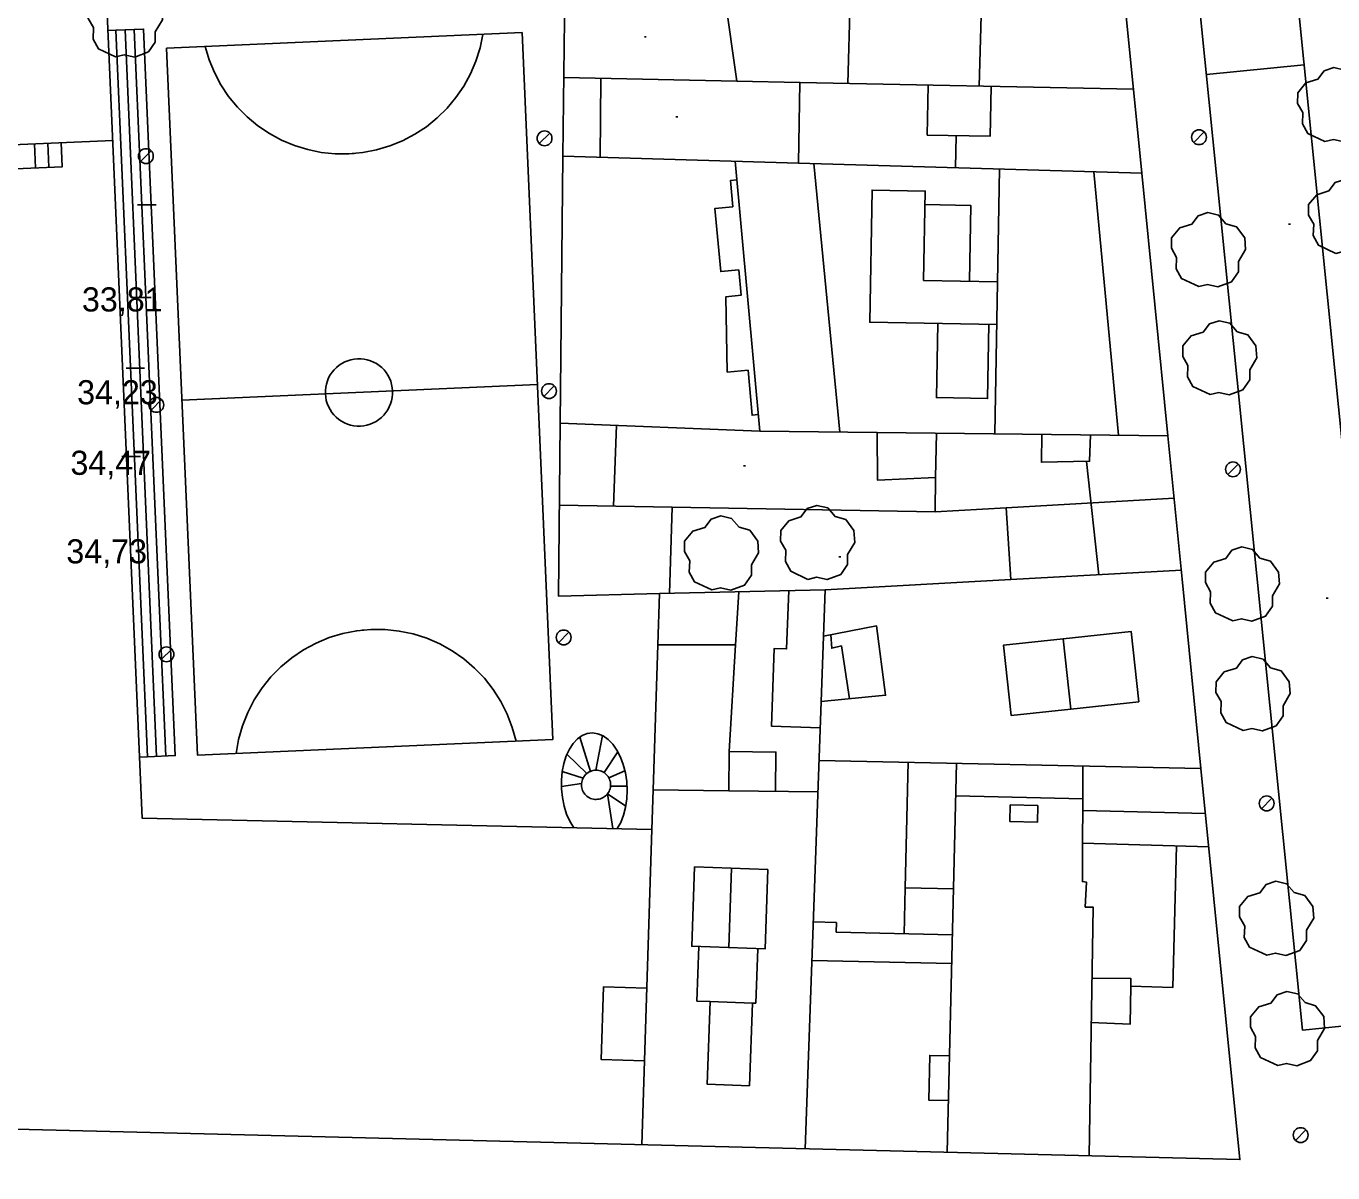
# Model space of a CAD drawing. Extents: x 431390 to 432653, y 4586754 to 4589600.
# Drawn here: x 431799.8 to 431870.2, y 4586845.3 to 4586907.1 of the extents above; entities that cross this region are included whole.
import ezdxf

# ---------------------------------------------------------------- set-up
doc = ezdxf.new("R2010")
doc.units = 0
for name, color, linetype in [('COM_17LS_LN', 7, 'Continuous'), ('COM_51_LN', 7, 'Continuous'), ('CON_01_LN', 7, 'Continuous'), ('CON_01FI_LN', 7, 'Continuous'), ('CON_03_LN', 7, 'Continuous'), ('CON_04_LN', 7, 'Continuous'), ('CON_07_LN', 7, 'Continuous'), ('CON_16_LN', 7, 'Continuous'), ('CON_18LS_LN', 7, 'Continuous'), ('CON_23_LN', 7, 'Continuous'), ('CON_24LS_LN', 7, 'Continuous'), ('CON_29_LN', 7, 'Continuous'), ('ENE_06_PT', 7, 'Continuous'), ('ORO_03_PT', 7, 'Continuous'), ('ORO_04_PT', 7, 'Continuous'), ('ORO_04_TX', 7, 'Continuous'), ('VEG_03_PT', 7, 'Continuous')]:
    doc.layers.add(name, color=color, linetype=linetype)

msp = doc.modelspace()

# ---------------------------------------------------------------- linework, layer by layer
at = {"layer": 'COM_17LS_LN'}
for points in [[(431853.209, 4587026.07), (431851.172, 4587025.865), (431854.479, 4586993.032), (431857.953, 4586958.536), (431861.124, 4586927.05), (431865.053, 4586888.028), (431868.58, 4586853.01), (431870.706, 4586853.224), (431871.5, 4586845.327)], [(431874.91, 4586845.69), (431873.853, 4586853.541), (431873.729, 4586854.767), (431875.087, 4586854.904), (431874.927, 4586856.495), (431873.569, 4586856.358), (431870.326, 4586888.559), (431867.823, 4586913.416), (431874.552, 4586914.603), (431895.864, 4586918.311), (431912.821, 4586921.261), (431929.172, 4586924.106), (431935.982, 4586925.291)]]:
    msp.add_lwpolyline(points, dxfattribs=at)
at = {"layer": 'COM_51_LN'}
msp.add_lwpolyline([(431863.395, 4586904.496), (431868.668, 4586905.027)], dxfattribs=at)
at = {"layer": 'CON_01_LN'}
for points in [[(431859.921, 4586899.186), (431858.937, 4586909.088)], [(431859.921, 4586899.186), (431861.326, 4586885.04)], [(431862.094, 4586877.312), (431861.326, 4586885.04)], [(431862.094, 4586877.312), (431863.106, 4586867.117)], [(431797.74, 4586847.72), (431865.2, 4586846.04), (431863.106, 4586867.117)]]:
    msp.add_lwpolyline(points, dxfattribs=at)
at = {"layer": 'CON_01FI_LN'}
for points in [[(431801.98, 4586957.34), (431806.03, 4586864.43), (431833.508, 4586863.83), (431833.576, 4586865.966), (431837.653, 4586865.916), (431837.679, 4586868.022), (431838.021, 4586873.777), (431833.823, 4586873.778), (431833.91, 4586876.529), (431842.85, 4586876.74), (431852.851, 4586877.287), (431852.6, 4586881.16), (431848.78, 4586880.94), (431848.8, 4586882.78), (431845.66, 4586882.65), (431845.641, 4586885.215), (431839.319, 4586885.285), (431828.566, 4586885.721)], [(431828.804, 4586908.95), (431837.436, 4586908.702), (431838.09, 4586904.139), (431841.489, 4586904.07), (431841.411, 4586899.722), (431828.713, 4586900.09), (431828.566, 4586885.721)]]:
    msp.add_lwpolyline(points, dxfattribs=at)
at = {"layer": 'CON_03_LN'}
for points in [[(431841.489, 4586904.07), (431859.472, 4586903.704)], [(431841.411, 4586899.722), (431859.921, 4586899.186)], [(431861.326, 4586885.04), (431845.641, 4586885.215)], [(431852.6, 4586881.16), (431861.66, 4586881.676)], [(431852.851, 4586877.287), (431862.046, 4586877.79)], [(431842.85, 4586876.74), (431841.773, 4586846.623)], [(431842.521, 4586867.545), (431863.106, 4586867.117)], [(431849.421, 4586846.433), (431849.925, 4586867.391)], [(431857.069, 4586846.242), (431857.29, 4586859.64), (431856.87, 4586859.64), (431856.93, 4586860.99), (431856.71, 4586861.02), (431856.744, 4586867.249)], [(431833.508, 4586863.83), (431832.97, 4586846.843)]]:
    msp.add_lwpolyline(points, dxfattribs=at)
at = {"layer": 'CON_04_LN'}
for points in [[(431844.202, 4586908.507), (431844.073, 4586904.017)], [(431851.281, 4586908.304), (431851.154, 4586903.873)], [(431804.438, 4586900.95), (431792.778, 4586900.442), (431792.621, 4586904.037), (431788.322, 4586903.85)], [(431851.787, 4586903.86), (431851.732, 4586901.169), (431848.35, 4586901.238), (431848.405, 4586903.929)], [(431837.991, 4586899.821), (431839.319, 4586885.285)], [(431843.636, 4586885.237), (431842.239, 4586899.698)], [(431852, 4586885.144), (431852.251, 4586899.408)], [(431858.667, 4586885.07), (431857.33, 4586899.261)], [(431838.083, 4586898.816), (431837.734, 4586898.784), (431837.863, 4586897.373), (431836.907, 4586897.286), (431837.218, 4586893.883), (431838.191, 4586893.972), (431838.316, 4586892.603), (431837.495, 4586892.528), (431837.571, 4586888.466), (431838.687, 4586888.568), (431838.909, 4586886.143), (431839.238, 4586886.173)], [(431852.104, 4586891.032), (431845.25, 4586891.153), (431845.375, 4586898.27), (431848.24, 4586898.22), (431848.155, 4586893.402), (431852.144, 4586893.332)], [(431850.619, 4586893.359), (431850.691, 4586897.443), (431848.227, 4586897.486)], [(431848.918, 4586891.088), (431848.847, 4586887.089), (431851.603, 4586887.04), (431851.674, 4586891.04)], [(431848.8, 4586882.78), (431848.841, 4586885.179)], [(431854.53, 4586885.116), (431854.5, 4586883.61), (431857.1, 4586883.66), (431857.151, 4586885.087)], [(431838.021, 4586873.777), (431838.19, 4586876.63)], [(431842.584, 4586869.297), (431839.951, 4586869.391), (431840.101, 4586873.576), (431840.769, 4586873.552), (431840.881, 4586876.694)], [(431842.635, 4586870.716), (431846.1, 4586871.06), (431845.62, 4586874.79), (431842.76, 4586874.234)], [(431844.154, 4586870.867), (431843.72, 4586873.71), (431843.2, 4586873.59), (431843.15, 4586874.31)], [(431855.682, 4586874.097), (431852.459, 4586873.751), (431852.866, 4586869.966), (431856.088, 4586870.312)], [(431859.756, 4586870.705), (431859.35, 4586874.49), (431855.682, 4586874.097), (431856.088, 4586870.312), (431859.756, 4586870.705)], [(431837.679, 4586868.022), (431840.189, 4586867.991), (431840.163, 4586865.885)], [(431847.161, 4586860.686), (431847.324, 4586867.445)], [(431842.461, 4586865.857), (431837.653, 4586865.916)], [(431856.734, 4586865.48), (431849.883, 4586865.64)], [(431854.311, 4586865.109), (431854.29, 4586864.211), (431852.802, 4586864.246), (431852.823, 4586865.144), (431854.311, 4586865.109)], [(431863.348, 4586864.681), (431856.731, 4586864.85)], [(431863.526, 4586862.893), (431856.721, 4586863.083)], [(431861.777, 4586862.942), (431861.59, 4586855.32), (431859.33, 4586855.39), (431859.33, 4586855.79), (431857.227, 4586855.821)], [(431839.762, 4586861.667), (431835.804, 4586861.809), (431835.651, 4586857.532), (431839.609, 4586857.39), (431839.762, 4586861.667)], [(431847.101, 4586858.207), (431847.161, 4586860.686), (431849.762, 4586860.623)], [(431849.703, 4586858.144), (431843.441, 4586858.295), (431843.453, 4586858.811), (431842.21, 4586858.841)], [(431836.036, 4586857.518), (431835.932, 4586854.583), (431836.648, 4586854.558)], [(431839.211, 4586857.404), (431839.107, 4586854.47), (431838.935, 4586854.476)], [(431849.666, 4586856.611), (431842.136, 4586856.763)], [(431833.237, 4586855.283), (431830.897, 4586855.357), (431830.773, 4586851.43), (431833.113, 4586851.356)], [(431859.33, 4586855.39), (431859.29, 4586853.34), (431857.188, 4586853.43)], [(431838.775, 4586850.014), (431836.488, 4586850.096), (431836.648, 4586854.558), (431838.935, 4586854.476), (431838.775, 4586850.014)], [(431849.546, 4586851.63), (431848.487, 4586851.656), (431848.429, 4586849.25), (431849.488, 4586849.225)]]:
    msp.add_lwpolyline(points, dxfattribs=at)
at = {"layer": 'CON_07_LN'}
for points in [[(431830.761, 4586904.288), (431830.708, 4586900.032)], [(431828.566, 4586885.721), (431828.47, 4586876.4), (431833.91, 4586876.529)], [(431831.591, 4586885.598), (431831.44, 4586881.242)], [(431828.52, 4586881.292), (431834.592, 4586881.187), (431834.46, 4586876.542)]]:
    msp.add_lwpolyline(points, dxfattribs=at)
at = {"layer": 'CON_16_LN'}
for points in [[(431828.713, 4586900.09), (431828.804, 4586908.95)], [(431838.09, 4586904.139), (431828.757, 4586904.329)], [(431848.78, 4586880.94), (431834.592, 4586881.187)], [(431833.576, 4586865.966), (431833.823, 4586873.778)]]:
    msp.add_lwpolyline(points, dxfattribs=at)
at = {"layer": 'CON_18LS_LN'}
for points in [[(431804.18, 4586906.865), (431804.603, 4586906.883), (431806.104, 4586906.948), (431807.809, 4586867.804), (431806.309, 4586867.739), (431805.887, 4586867.721)], [(431805.104, 4586906.905), (431806.809, 4586867.761)], [(431805.604, 4586906.926), (431807.309, 4586867.782)], [(431804.603, 4586906.883), (431806.309, 4586867.739)]]:
    msp.add_lwpolyline(points, dxfattribs=at)
at = {"layer": 'CON_23_LN'}
for points in [[(431794.467, 4586900.516), (431794.524, 4586899.217), (431801.717, 4586899.53), (431801.66, 4586900.829)], [(431800.221, 4586900.766), (431800.278, 4586899.467)], [(431800.941, 4586900.798), (431800.997, 4586899.499)], [(431829.292, 4586863.922), (431829.083, 4586864.267), (431828.909, 4586864.659), (431828.773, 4586865.088), (431828.679, 4586865.543), (431828.63, 4586866.013), (431828.627, 4586866.485), (431828.669, 4586866.947), (431828.757, 4586867.387), (431828.887, 4586867.793), (431829.056, 4586868.155), (431829.26, 4586868.464), (431829.494, 4586868.711), (431829.751, 4586868.891), (431830.025, 4586868.998), (431830.308, 4586869.03), (431830.594, 4586868.986), (431830.875, 4586868.867), (431831.143, 4586868.676), (431831.392, 4586868.418), (431831.616, 4586868.099), (431831.807, 4586867.729), (431831.963, 4586867.317), (431832.077, 4586866.873), (431832.148, 4586866.408), (431832.174, 4586865.936), (431832.154, 4586865.468), (431832.088, 4586865.016), (431831.978, 4586864.592), (431831.828, 4586864.207), (431831.64, 4586863.871)], [(431830.489, 4586867.019), (431830.838, 4586868.883)], [(431830.188, 4586866.956), (431829.621, 4586868.8)], [(431829.991, 4586866.836), (431828.925, 4586867.874)], [(431830.927, 4586866.891), (431831.667, 4586868.001)], [(431829.799, 4586866.596), (431828.669, 4586866.942)], [(431831.11, 4586865.74), (431831.059, 4586865.682), (431831.002, 4586865.63), (431830.941, 4586865.583), (431830.875, 4586865.543), (431830.805, 4586865.509), (431830.733, 4586865.482), (431830.658, 4586865.463), (431830.582, 4586865.451), (431830.505, 4586865.446), (431830.428, 4586865.449), (431830.351, 4586865.46), (431830.276, 4586865.478), (431830.203, 4586865.503), (431830.133, 4586865.535), (431830.066, 4586865.574), (431830.004, 4586865.619), (431829.946, 4586865.671), (431829.894, 4586865.727), (431829.847, 4586865.789), (431829.807, 4586865.855), (431829.773, 4586865.924), (431829.746, 4586865.997), (431829.727, 4586866.071), (431829.715, 4586866.148), (431829.71, 4586866.225), (431829.713, 4586866.302), (431829.724, 4586866.378), (431829.742, 4586866.453), (431829.767, 4586866.526), (431829.799, 4586866.596), (431829.838, 4586866.663), (431829.883, 4586866.726), (431829.935, 4586866.783), (431829.991, 4586866.836), (431830.053, 4586866.882), (431830.119, 4586866.923), (431830.188, 4586866.956), (431830.261, 4586866.983), (431830.335, 4586867.003), (431830.412, 4586867.015), (431830.489, 4586867.019), (431830.566, 4586867.016), (431830.642, 4586867.006), (431830.717, 4586866.988), (431830.79, 4586866.963), (431830.86, 4586866.93), (431830.927, 4586866.891), (431830.989, 4586866.846), (431831.047, 4586866.795), (431831.1, 4586866.738), (431831.146, 4586866.677), (431831.187, 4586866.611), (431831.22, 4586866.541), (431831.247, 4586866.469), (431831.267, 4586866.394), (431831.279, 4586866.318), (431831.283, 4586866.241), (431831.28, 4586866.164), (431831.27, 4586866.087), (431831.252, 4586866.012), (431831.227, 4586865.939), (431831.194, 4586865.869), (431831.155, 4586865.802), (431831.11, 4586865.74)], [(431831.187, 4586866.611), (431832.046, 4586866.992)], [(431829.713, 4586866.302), (431828.629, 4586866.142)], [(431831.28, 4586866.164), (431832.161, 4586866.165)], [(431831.11, 4586865.74), (431831.395, 4586863.876)], [(431831.11, 4586865.74), (431832.098, 4586865.088)]]:
    msp.add_lwpolyline(points, dxfattribs=at)
at = {"layer": 'CON_24LS_LN'}
for points in [[(431807.342, 4586905.916), (431826.504, 4586906.752), (431828.165, 4586868.67), (431809.003, 4586867.834), (431807.342, 4586905.916)], [(431824.397, 4586906.66), (431824.243, 4586905.928), (431824.018, 4586905.215), (431823.725, 4586904.527), (431823.366, 4586903.871), (431822.945, 4586903.253), (431822.466, 4586902.68), (431821.932, 4586902.155), (431821.35, 4586901.686), (431820.725, 4586901.275), (431820.063, 4586900.928), (431819.371, 4586900.646), (431818.654, 4586900.434), (431817.919, 4586900.292), (431817.175, 4586900.223), (431816.427, 4586900.227), (431815.683, 4586900.304), (431814.951, 4586900.454), (431814.236, 4586900.674), (431813.546, 4586900.962), (431812.888, 4586901.317), (431812.267, 4586901.734), (431811.691, 4586902.21), (431811.163, 4586902.74), (431810.689, 4586903.318), (431810.275, 4586903.941), (431809.923, 4586904.6), (431809.637, 4586905.291), (431809.42, 4586906.007)], [(431815.904, 4586887.29), (431815.921, 4586887.113), (431815.954, 4586886.938), (431816.005, 4586886.768), (431816.072, 4586886.603), (431816.155, 4586886.445), (431816.253, 4586886.297), (431816.366, 4586886.159), (431816.491, 4586886.032), (431816.628, 4586885.919), (431816.775, 4586885.819), (431816.932, 4586885.734), (431817.096, 4586885.665), (431817.266, 4586885.613), (431817.44, 4586885.577), (431817.617, 4586885.559), (431817.795, 4586885.558), (431817.972, 4586885.575), (431818.147, 4586885.608), (431818.317, 4586885.659), (431818.482, 4586885.726), (431818.64, 4586885.809), (431818.788, 4586885.907), (431818.926, 4586886.02), (431819.053, 4586886.145), (431819.166, 4586886.282), (431819.266, 4586886.429), (431819.351, 4586886.586), (431819.42, 4586886.75), (431819.472, 4586886.92), (431819.508, 4586887.094), (431819.526, 4586887.271), (431819.527, 4586887.449), (431819.51, 4586887.626), (431819.477, 4586887.801), (431819.426, 4586887.971), (431819.359, 4586888.136), (431819.276, 4586888.294), (431819.178, 4586888.442), (431819.065, 4586888.58), (431818.94, 4586888.707), (431818.803, 4586888.82), (431818.656, 4586888.92), (431818.499, 4586889.005), (431818.335, 4586889.074), (431818.165, 4586889.126), (431817.991, 4586889.162), (431817.814, 4586889.18), (431817.636, 4586889.181), (431817.459, 4586889.164), (431817.284, 4586889.131), (431817.114, 4586889.08), (431816.949, 4586889.013), (431816.791, 4586888.93), (431816.643, 4586888.832), (431816.505, 4586888.719), (431816.378, 4586888.594), (431816.265, 4586888.457), (431816.165, 4586888.31), (431816.08, 4586888.153), (431816.011, 4586887.989), (431815.959, 4586887.819), (431815.923, 4586887.645), (431815.905, 4586887.468), (431815.904, 4586887.29)], [(431808.169, 4586886.953), (431827.331, 4586887.789)], [(431826.182, 4586868.583), (431825.981, 4586869.322), (431825.708, 4586870.037), (431825.364, 4586870.721), (431824.954, 4586871.367), (431824.482, 4586871.969), (431823.951, 4586872.522), (431823.369, 4586873.018), (431822.739, 4586873.454), (431822.07, 4586873.825), (431821.367, 4586874.127), (431820.637, 4586874.358), (431819.887, 4586874.515), (431819.126, 4586874.596), (431818.361, 4586874.601), (431817.599, 4586874.529), (431816.847, 4586874.382), (431816.115, 4586874.161), (431815.407, 4586873.868), (431814.733, 4586873.505), (431814.098, 4586873.077), (431813.51, 4586872.588), (431812.972, 4586872.043), (431812.492, 4586871.447), (431812.074, 4586870.805), (431811.722, 4586870.126), (431811.439, 4586869.414), (431811.229, 4586868.678), (431811.093, 4586867.925)]]:
    msp.add_lwpolyline(points, dxfattribs=at)
at = {"layer": 'CON_29_LN'}
for points in [[(431849.911, 4586901.206), (431849.876, 4586899.477)], [(431857.59, 4586877.546), (431856.942, 4586883.657)], [(431837.652, 4586857.46), (431837.805, 4586861.737)]]:
    msp.add_lwpolyline(points, dxfattribs=at)
at = {"layer": 'ENE_06_PT'}
for p, q in [((431828.002, 4586901.342), (431827.436, 4586900.776)), ((431863.282, 4586901.402), (431862.716, 4586900.836)), ((431806.512, 4586900.382), (431805.946, 4586899.816)), ((431828.242, 4586887.722), (431827.676, 4586887.156)), ((431807.072, 4586886.982), (431806.506, 4586886.416)), ((431865.112, 4586883.512), (431864.546, 4586882.946)), ((431829.032, 4586874.452), (431828.466, 4586873.886)), ((431807.622, 4586873.542), (431807.056, 4586872.976)), ((431866.932, 4586865.512), (431866.366, 4586864.946)), ((431868.762, 4586847.642), (431868.196, 4586847.076))]:
    msp.add_line(p, q, dxfattribs=at)
for centre in [(431827.719, 4586901.059), (431862.999, 4586901.119), (431806.229, 4586900.099), (431827.959, 4586887.439), (431806.789, 4586886.699), (431864.829, 4586883.229), (431828.749, 4586874.169), (431807.339, 4586873.259), (431866.649, 4586865.229), (431868.479, 4586847.359)]:
    msp.add_circle(centre, 0.4, dxfattribs=at)
at = {"layer": 'ORO_03_PT'}
for p, q in [((431833.1, 4586906.52), (431833.2, 4586906.52)), ((431834.8, 4586902.22), (431834.9, 4586902.22)), ((431817.35, 4586900.244), (431817.45, 4586900.244)), ((431867.825, 4586896.433), (431867.925, 4586896.433)), ((431838.45, 4586883.41), (431838.55, 4586883.41)), ((431843.59, 4586878.51), (431843.69, 4586878.51)), ((431869.854, 4586876.281), (431869.954, 4586876.281)), ((431817.883, 4586874.561), (431817.983, 4586874.561))]:
    msp.add_line(p, q, dxfattribs=at)
at = {"layer": 'ORO_04_PT'}
for p, q in [((431805.78, 4586897.48), (431806.78, 4586897.48)), ((431805.52, 4586892.48), (431806.52, 4586892.48)), ((431805.16, 4586888.68), (431806.16, 4586888.68)), ((431804.94, 4586883.91), (431805.94, 4586883.91))]:
    msp.add_line(p, q, dxfattribs=at)
at = {"layer": 'VEG_03_PT'}
for points in [[(431804.594, 4586905.451), (431803.667, 4586905.886), (431803.379, 4586906.407), (431803.402, 4586907.021), (431803.12, 4586907.513), (431803.128, 4586908.076), (431803.569, 4586908.611), (431804.222, 4586908.815), (431804.557, 4586909.266), (431805.083, 4586909.436), (431805.663, 4586909.303), (431806.063, 4586908.837), (431806.637, 4586908.667), (431807.071, 4586908.084), (431807.12, 4586907.442), (431806.737, 4586906.795), (431806.737, 4586906.245), (431806.365, 4586905.711), (431805.626, 4586905.436), (431805.061, 4586905.564), (431804.594, 4586905.451)], [(431869.784, 4586900.881), (431868.857, 4586901.316), (431868.569, 4586901.837), (431868.592, 4586902.451), (431868.31, 4586902.943), (431868.318, 4586903.506), (431868.759, 4586904.041), (431869.412, 4586904.245), (431869.747, 4586904.696), (431870.273, 4586904.866), (431870.853, 4586904.733), (431871.253, 4586904.267), (431871.827, 4586904.097), (431872.261, 4586903.514), (431872.31, 4586902.872), (431871.927, 4586902.225), (431871.927, 4586901.675), (431871.555, 4586901.141), (431870.816, 4586900.866), (431870.251, 4586900.994), (431869.784, 4586900.881)], [(431870.374, 4586894.861), (431869.447, 4586895.296), (431869.159, 4586895.817), (431869.182, 4586896.431), (431868.9, 4586896.923), (431868.908, 4586897.486), (431869.349, 4586898.021), (431870.002, 4586898.225), (431870.337, 4586898.676), (431870.863, 4586898.846), (431871.443, 4586898.713), (431871.843, 4586898.247), (431872.417, 4586898.077), (431872.851, 4586897.494), (431872.9, 4586896.852), (431872.517, 4586896.205), (431872.517, 4586895.655), (431872.145, 4586895.121), (431871.406, 4586894.846), (431870.841, 4586894.974), (431870.374, 4586894.861)], [(431862.984, 4586893.071), (431862.057, 4586893.506), (431861.769, 4586894.027), (431861.792, 4586894.641), (431861.51, 4586895.133), (431861.518, 4586895.696), (431861.959, 4586896.231), (431862.612, 4586896.435), (431862.947, 4586896.886), (431863.473, 4586897.056), (431864.053, 4586896.923), (431864.453, 4586896.457), (431865.027, 4586896.287), (431865.461, 4586895.704), (431865.51, 4586895.062), (431865.127, 4586894.415), (431865.127, 4586893.865), (431864.755, 4586893.331), (431864.016, 4586893.056), (431863.451, 4586893.184), (431862.984, 4586893.071)], [(431863.594, 4586887.251), (431862.667, 4586887.686), (431862.379, 4586888.207), (431862.402, 4586888.821), (431862.12, 4586889.313), (431862.128, 4586889.876), (431862.569, 4586890.411), (431863.222, 4586890.615), (431863.557, 4586891.066), (431864.083, 4586891.236), (431864.663, 4586891.103), (431865.063, 4586890.637), (431865.637, 4586890.467), (431866.071, 4586889.884), (431866.12, 4586889.242), (431865.737, 4586888.595), (431865.737, 4586888.045), (431865.365, 4586887.511), (431864.626, 4586887.236), (431864.061, 4586887.364), (431863.594, 4586887.251)], [(431841.914, 4586877.301), (431840.987, 4586877.736), (431840.699, 4586878.257), (431840.722, 4586878.871), (431840.44, 4586879.363), (431840.448, 4586879.926), (431840.889, 4586880.461), (431841.542, 4586880.665), (431841.877, 4586881.116), (431842.403, 4586881.286), (431842.983, 4586881.153), (431843.383, 4586880.687), (431843.957, 4586880.517), (431844.391, 4586879.934), (431844.44, 4586879.292), (431844.057, 4586878.645), (431844.057, 4586878.095), (431843.685, 4586877.561), (431842.946, 4586877.286), (431842.381, 4586877.414), (431841.914, 4586877.301)], [(431836.734, 4586876.731), (431835.807, 4586877.166), (431835.519, 4586877.687), (431835.542, 4586878.301), (431835.26, 4586878.793), (431835.268, 4586879.356), (431835.709, 4586879.891), (431836.362, 4586880.095), (431836.697, 4586880.546), (431837.223, 4586880.716), (431837.803, 4586880.583), (431838.203, 4586880.117), (431838.777, 4586879.947), (431839.211, 4586879.364), (431839.26, 4586878.722), (431838.877, 4586878.075), (431838.877, 4586877.525), (431838.505, 4586876.991), (431837.766, 4586876.716), (431837.201, 4586876.844), (431836.734, 4586876.731)], [(431864.814, 4586875.061), (431863.887, 4586875.496), (431863.599, 4586876.017), (431863.622, 4586876.631), (431863.34, 4586877.123), (431863.348, 4586877.686), (431863.789, 4586878.221), (431864.442, 4586878.425), (431864.777, 4586878.876), (431865.303, 4586879.046), (431865.883, 4586878.913), (431866.283, 4586878.447), (431866.857, 4586878.277), (431867.291, 4586877.694), (431867.34, 4586877.052), (431866.957, 4586876.405), (431866.957, 4586875.855), (431866.585, 4586875.321), (431865.846, 4586875.046), (431865.281, 4586875.174), (431864.814, 4586875.061)], [(431865.384, 4586869.151), (431864.457, 4586869.586), (431864.169, 4586870.107), (431864.192, 4586870.721), (431863.91, 4586871.213), (431863.918, 4586871.776), (431864.359, 4586872.311), (431865.012, 4586872.515), (431865.347, 4586872.966), (431865.873, 4586873.136), (431866.453, 4586873.003), (431866.853, 4586872.537), (431867.427, 4586872.367), (431867.861, 4586871.784), (431867.91, 4586871.142), (431867.527, 4586870.495), (431867.527, 4586869.945), (431867.155, 4586869.411), (431866.416, 4586869.136), (431865.851, 4586869.264), (431865.384, 4586869.151)], [(431866.654, 4586857.051), (431865.727, 4586857.486), (431865.439, 4586858.007), (431865.462, 4586858.621), (431865.18, 4586859.113), (431865.188, 4586859.676), (431865.629, 4586860.211), (431866.282, 4586860.415), (431866.617, 4586860.866), (431867.143, 4586861.036), (431867.723, 4586860.903), (431868.123, 4586860.437), (431868.697, 4586860.267), (431869.131, 4586859.684), (431869.18, 4586859.042), (431868.797, 4586858.395), (431868.797, 4586857.845), (431868.425, 4586857.311), (431867.686, 4586857.036), (431867.121, 4586857.164), (431866.654, 4586857.051)], [(431867.244, 4586851.111), (431866.317, 4586851.546), (431866.029, 4586852.067), (431866.052, 4586852.681), (431865.77, 4586853.173), (431865.778, 4586853.736), (431866.219, 4586854.271), (431866.872, 4586854.475), (431867.207, 4586854.926), (431867.733, 4586855.096), (431868.313, 4586854.963), (431868.713, 4586854.497), (431869.287, 4586854.327), (431869.721, 4586853.744), (431869.77, 4586853.102), (431869.387, 4586852.455), (431869.387, 4586851.905), (431869.015, 4586851.371), (431868.276, 4586851.096), (431867.711, 4586851.224), (431867.244, 4586851.111)]]:
    msp.add_lwpolyline(points, dxfattribs=at)

# ---------------------------------------------------------------- texts
at = {"layer": 'ORO_04_TX'}
for s, p in [('33,81', (431802.78, 4586891.73)), ('34,23', (431802.52, 4586886.73)), ('34,47', (431802.16, 4586882.93)), ('34,73', (431801.94, 4586878.16))]:
    msp.add_text(s, height=1.3, dxfattribs=at).set_placement(p)

doc.saveas('drawing.dxf')
